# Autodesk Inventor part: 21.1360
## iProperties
Created: 2006-12
Part Number: 21.1360
Document SubType Name: Modeling
Designer: Andy Moles
Material: Steel, Mild
Mass: 1.8265 g
Surface Area: 3.87902 cm^2
Volume: 0.23238 cm^3
Density: 7.86 g/cm^3
Author: Andy Moles
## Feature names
1. Extrusion1
